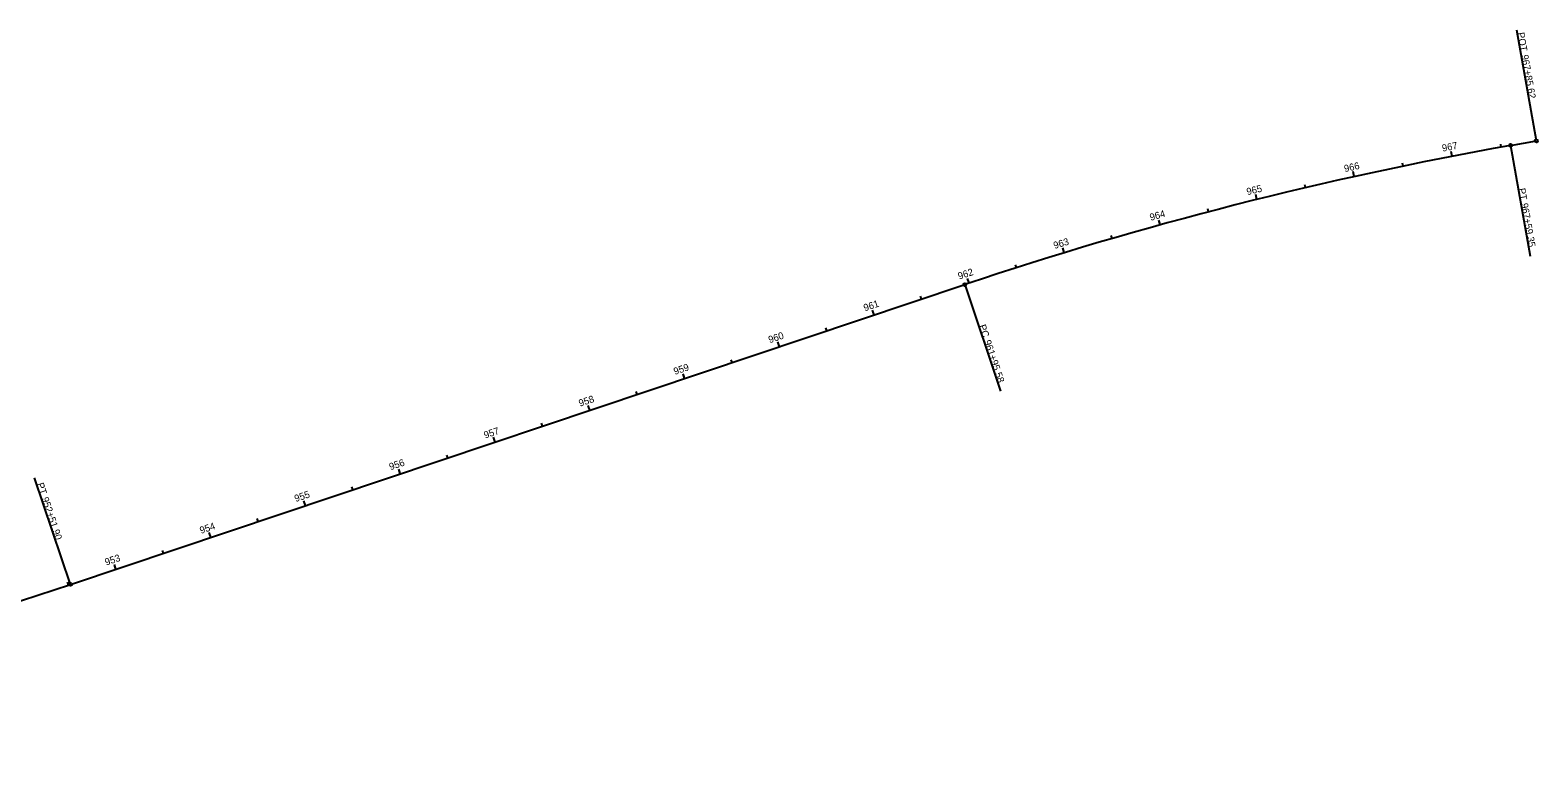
# Model space of a CAD drawing. Extents: x 2189048 to 2198002, y 659562 to 661773.
# Drawn here: x 2190546 to 2192054, y 659580 to 660330 of the extents above; entities that cross this region are included whole.
import ezdxf

# ---------------------------------------------------------------- set-up
doc = ezdxf.new("R2010")
doc.units = 0
for name, color, linetype in [('GE_X_Alignment', 7, 'Continuous'), ('GE_X_Alignment_1000_Stations', 7, 'Continuous'), ('GE_X_Alignment_100_Stations', 7, 'Continuous'), ('GE_X_Alignment_500_Stations', 7, 'Continuous')]:
    doc.layers.add(name, color=color, linetype=linetype)

msp = doc.modelspace()

# ---------------------------------------------------------------- linework, layer by layer
at = {"layer": 'GE_X_Alignment'}
for p, q in [((2192026.6, 660214.2), (2192052.5, 660218.8)), ((2190586.1, 659775.1), (2191480.8, 660075.1))]:
    msp.add_line(p, q, dxfattribs=at)
for centre, start, end in [((2192694.9, 656453.4), 100.0763, 108.5329), ((2189372, 663396.7), 272.0655, 288.5329)]:
    msp.add_arc(centre, 3819.7, start, end, dxfattribs=at)
at = {"layer": 'GE_X_Alignment_1000_Stations'}
for p, q in [((2192052.5, 660218.8), (2192032.8, 660329.6)), ((2192026.6, 660214.2), (2192046.3, 660103.5)), ((2191773, 660160.2), (2191772.3, 660163.1)), ((2191480.8, 660075.1), (2191516.6, 659968.4)), ((2191295.4, 660012.9), (2191293.8, 660017.6)), ((2190586.1, 659775.1), (2190550.3, 659881.8)), ((2190821.3, 659854), (2190820.3, 659856.8))]:
    msp.add_line(p, q, dxfattribs=at)
for centre in [(2192026.6, 660214.2), (2192052.5, 660218.8), (2191480.8, 660075.1), (2190586.1, 659775.1)]:
    msp.add_circle(centre, 1.5, dxfattribs=at)
at = {"layer": 'GE_X_Alignment_100_Stations'}
for p, q in [((2192052.5, 660218.8), (2192032.8, 660329.6)), ((2192017.4, 660212.6), (2192016.9, 660215.5)), ((2192026.6, 660214.2), (2192046.3, 660103.5)), ((2191968.2, 660203.4), (2191967.3, 660208.3)), ((2191870.3, 660183.1), (2191869.3, 660188)), ((2191919.2, 660193.6), (2191918.6, 660196.5)), ((2191821.6, 660172), (2191820.9, 660174.9)), ((2191773, 660160.2), (2191771.8, 660165.1)), ((2191676.3, 660134.8), (2191674.9, 660139.6)), ((2191724.5, 660147.8), (2191723.8, 660150.7)), ((2191628.2, 660121.2), (2191627.3, 660124)), ((2191580.2, 660106.9), (2191578.8, 660111.7)), ((2191532.5, 660092), (2191531.6, 660094.8)), ((2191485, 660076.5), (2191483.4, 660081.2)), ((2191437.6, 660060.6), (2191436.6, 660063.4)), ((2191480.8, 660075.1), (2191516.6, 659968.4)), ((2191390.2, 660044.7), (2191388.6, 660049.4)), ((2191295.4, 660012.9), (2191293.8, 660017.6)), ((2191342.8, 660028.8), (2191341.8, 660031.6)), ((2191248, 659997), (2191247, 659999.8)), ((2191200.5, 659981.1), (2191199, 659985.8)), ((2191153.1, 659965.2), (2191152.2, 659968.1)), ((2191105.7, 659949.3), (2191104.1, 659954.1)), ((2191058.3, 659933.4), (2191057.4, 659936.3)), ((2191010.9, 659917.5), (2191009.3, 659922.3)), ((2190963.5, 659901.6), (2190962.6, 659904.5)), ((2190586.1, 659775.1), (2190550.3, 659881.8)), ((2190916.1, 659885.7), (2190914.5, 659890.5)), ((2190868.7, 659869.9), (2190867.7, 659872.7)), ((2190821.3, 659854), (2190819.7, 659858.7)), ((2190773.9, 659838.1), (2190772.9, 659840.9)), ((2190726.5, 659822.2), (2190724.9, 659826.9)), ((2190679.1, 659806.3), (2190678.1, 659809.1)), ((2190631.7, 659790.4), (2190630.1, 659795.1)), ((2190584.3, 659774.5), (2190583.3, 659777.3))]:
    msp.add_line(p, q, dxfattribs=at)
for centre in [(2192026.6, 660214.2), (2192052.5, 660218.8), (2191480.8, 660075.1), (2190586.1, 659775.1)]:
    msp.add_circle(centre, 1.5, dxfattribs=at)
at = {"layer": 'GE_X_Alignment_500_Stations'}
for p, q in [((2192052.5, 660218.8), (2192032.8, 660329.6)), ((2192026.6, 660214.2), (2192046.3, 660103.5)), ((2191968.2, 660203.4), (2191967.7, 660206.3)), ((2191870.3, 660183.1), (2191869.7, 660186)), ((2191773, 660160.2), (2191771.8, 660165.1)), ((2191676.3, 660134.8), (2191675.5, 660137.7)), ((2191580.2, 660106.9), (2191579.4, 660109.8)), ((2191485, 660076.5), (2191484, 660079.3)), ((2191480.8, 660075.1), (2191516.6, 659968.4)), ((2191390.2, 660044.7), (2191389.2, 660047.5)), ((2191295.4, 660012.9), (2191293.8, 660017.6)), ((2191200.5, 659981.1), (2191199.6, 659983.9)), ((2191105.7, 659949.3), (2191104.8, 659952.2)), ((2191010.9, 659917.5), (2191010, 659920.4)), ((2190586.1, 659775.1), (2190550.3, 659881.8)), ((2190916.1, 659885.7), (2190915.2, 659888.6)), ((2190821.3, 659854), (2190819.7, 659858.7)), ((2190726.5, 659822.2), (2190725.5, 659825)), ((2190631.7, 659790.4), (2190630.7, 659793.2))]:
    msp.add_line(p, q, dxfattribs=at)
for centre in [(2192026.6, 660214.2), (2192052.5, 660218.8), (2191480.8, 660075.1), (2190586.1, 659775.1)]:
    msp.add_circle(centre, 1.5, dxfattribs=at)

# ---------------------------------------------------------------- texts
at = {"layer": 'GE_X_Alignment_1000_Stations'}
for s, rotation, p in [('POT', 280.0763, (2192033.4, 660326.8)), ('967+85.62', 280.0763, (2192037.4, 660304.4)), ('PT', 280.0763, (2192034.4, 660170.9)), ('967+59.35', 280.0763, (2192037.1, 660155.9)), ('PC', 288.5329, (2191494.8, 660033.8)), ('960', 18.5329, (2191285.6, 660016.3)), ('961+95.58', 288.5329, (2191499.9, 660018.3)), ('PT', 288.5329, (2190552.5, 659875.5)), ('952+51.90', 288.5329, (2190557.3, 659861.1))]:
    msp.add_text(s, height=7, rotation=rotation, dxfattribs=at).set_placement(p)
at = {"layer": 'GE_X_Alignment_100_Stations'}
for s, rotation, p in [('POT', 280.0763, (2192033.4, 660326.8)), ('967+85.62', 280.0763, (2192037.4, 660304.4)), ('967', 10.9666, (2191958.8, 660208)), ('966', 12.4666, (2191860.9, 660187.5)), ('965', 13.9666, (2191763.5, 660164.4)), ('PT', 280.0763, (2192034.4, 660170.9)), ('967+59.35', 280.0763, (2192037.1, 660155.9)), ('964', 15.4666, (2191666.8, 660138.8)), ('963', 16.9666, (2191570.6, 660110.6)), ('962', 18.4666, (2191475.2, 660079.9)), ('961', 18.5329, (2191380.8, 660048.2)), ('PC', 288.5329, (2191494.8, 660033.8)), ('960', 18.5329, (2191285.6, 660016.3)), ('961+95.58', 288.5329, (2191499.9, 660018.3)), ('959', 18.5329, (2191190.8, 659984.6)), ('958', 18.5329, (2191095.9, 659952.8)), ('957', 18.5329, (2191001, 659920.9)), ('956', 18.5329, (2190906.3, 659889.2)), ('PT', 288.5329, (2190552.5, 659875.5)), ('955', 18.5329, (2190811.5, 659857.4)), ('952+51.90', 288.5329, (2190557.3, 659861.1)), ('954', 18.5329, (2190716.8, 659825.6)), ('953', 18.5329, (2190621.9, 659793.8))]:
    msp.add_text(s, height=7, rotation=rotation, dxfattribs=at).set_placement(p)
at = {"layer": 'GE_X_Alignment_500_Stations'}
for s, rotation, p in [('POT', 280.0763, (2192033.4, 660326.8)), ('967+85.62', 280.0763, (2192037.4, 660304.4)), ('965', 13.9666, (2191763.5, 660164.4)), ('PT', 280.0763, (2192034.4, 660170.9)), ('967+59.35', 280.0763, (2192037.1, 660155.9)), ('PC', 288.5329, (2191494.8, 660033.8)), ('960', 18.5329, (2191285.6, 660016.3)), ('961+95.58', 288.5329, (2191499.9, 660018.3)), ('PT', 288.5329, (2190552.5, 659875.5)), ('955', 18.5329, (2190811.5, 659857.4)), ('952+51.90', 288.5329, (2190557.3, 659861.1))]:
    msp.add_text(s, height=7, rotation=rotation, dxfattribs=at).set_placement(p)

doc.saveas('drawing.dxf')
